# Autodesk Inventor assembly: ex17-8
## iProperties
Author: Elise Moss
Created: 2001-09
Part Number: ex17-8
Document SubType Name: Assembly
Designer: Elise Moss
Control State: 0
Master: False
Checked Out: False
PropertySet Name: Design Tracking Control
Shininess: 64.0
Angle Display Precision: 2
Document Length Units: 11269
Document Angle Units: 11283
Document Time Units: 11279
Document Mass Units: 11290
Document Length Units Precision: 3
Document Angle Units Precision: 2
Compacted: False
PropertySet Name: _Private Model Information
Density: 0.0
Volumn: 0.0
Area: 0.0
PropertySet Name: Model Information
